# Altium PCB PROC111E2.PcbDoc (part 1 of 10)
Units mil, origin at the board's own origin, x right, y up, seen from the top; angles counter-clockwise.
Board outline 7700 x 2300 mil, 6 copper layers (Top Layer, GND 1, SIG 1, SIG 2, GND 2, Bottom Layer), stack 78.711 mil thick; 767 components, 596 nets, 2755 pads, 1578 vias.
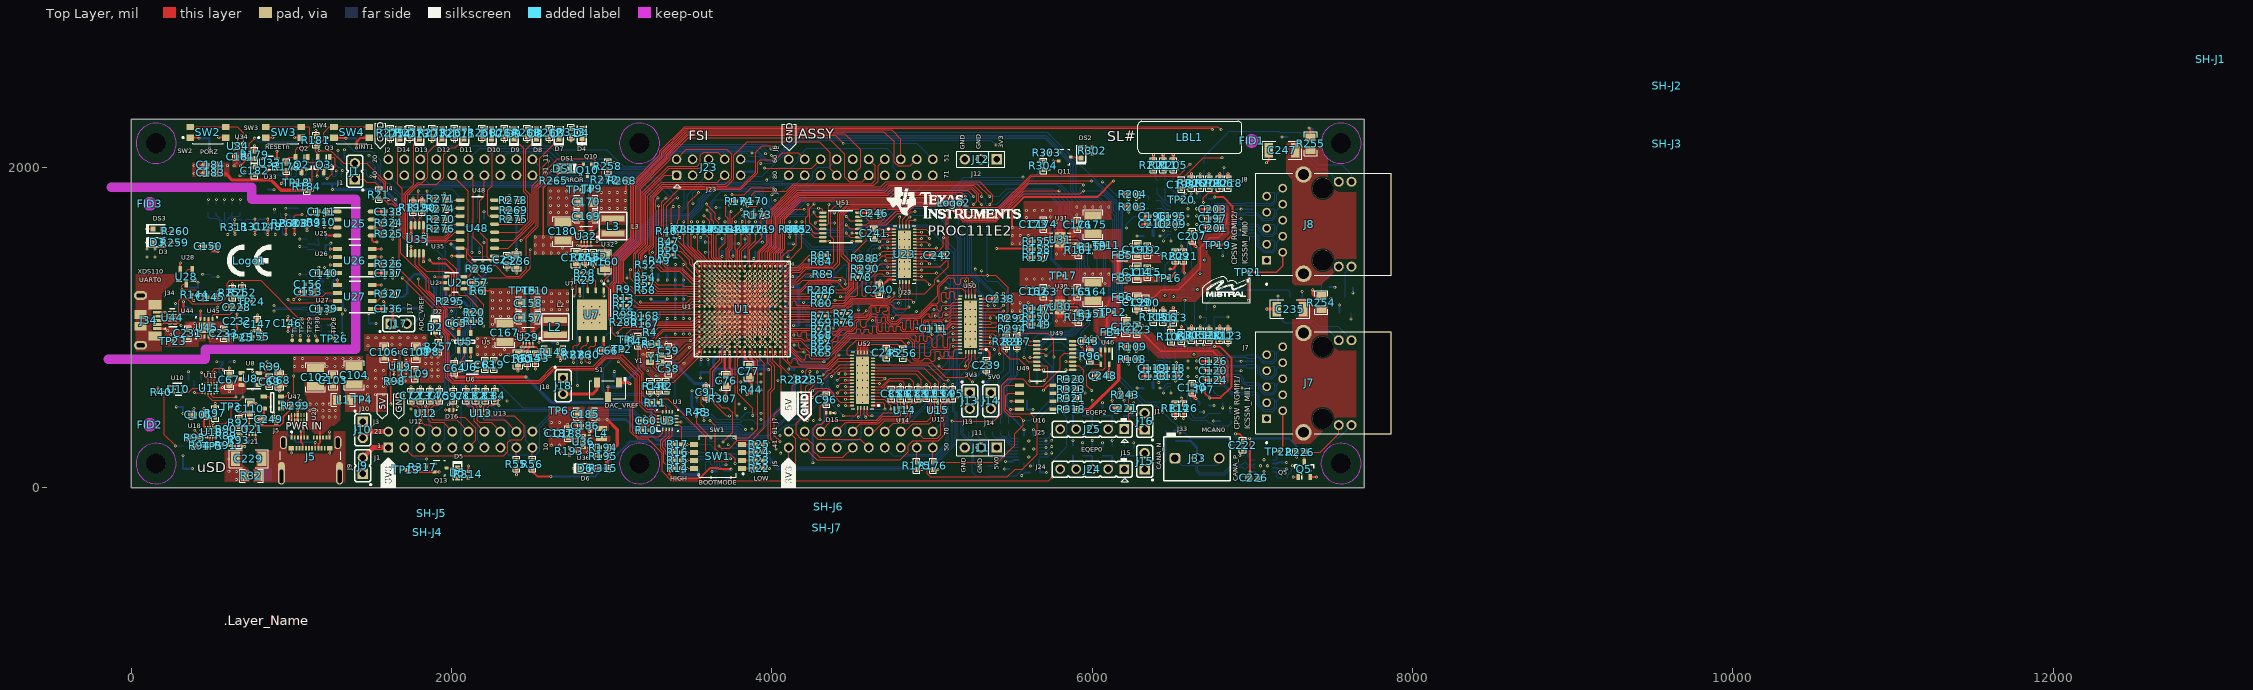
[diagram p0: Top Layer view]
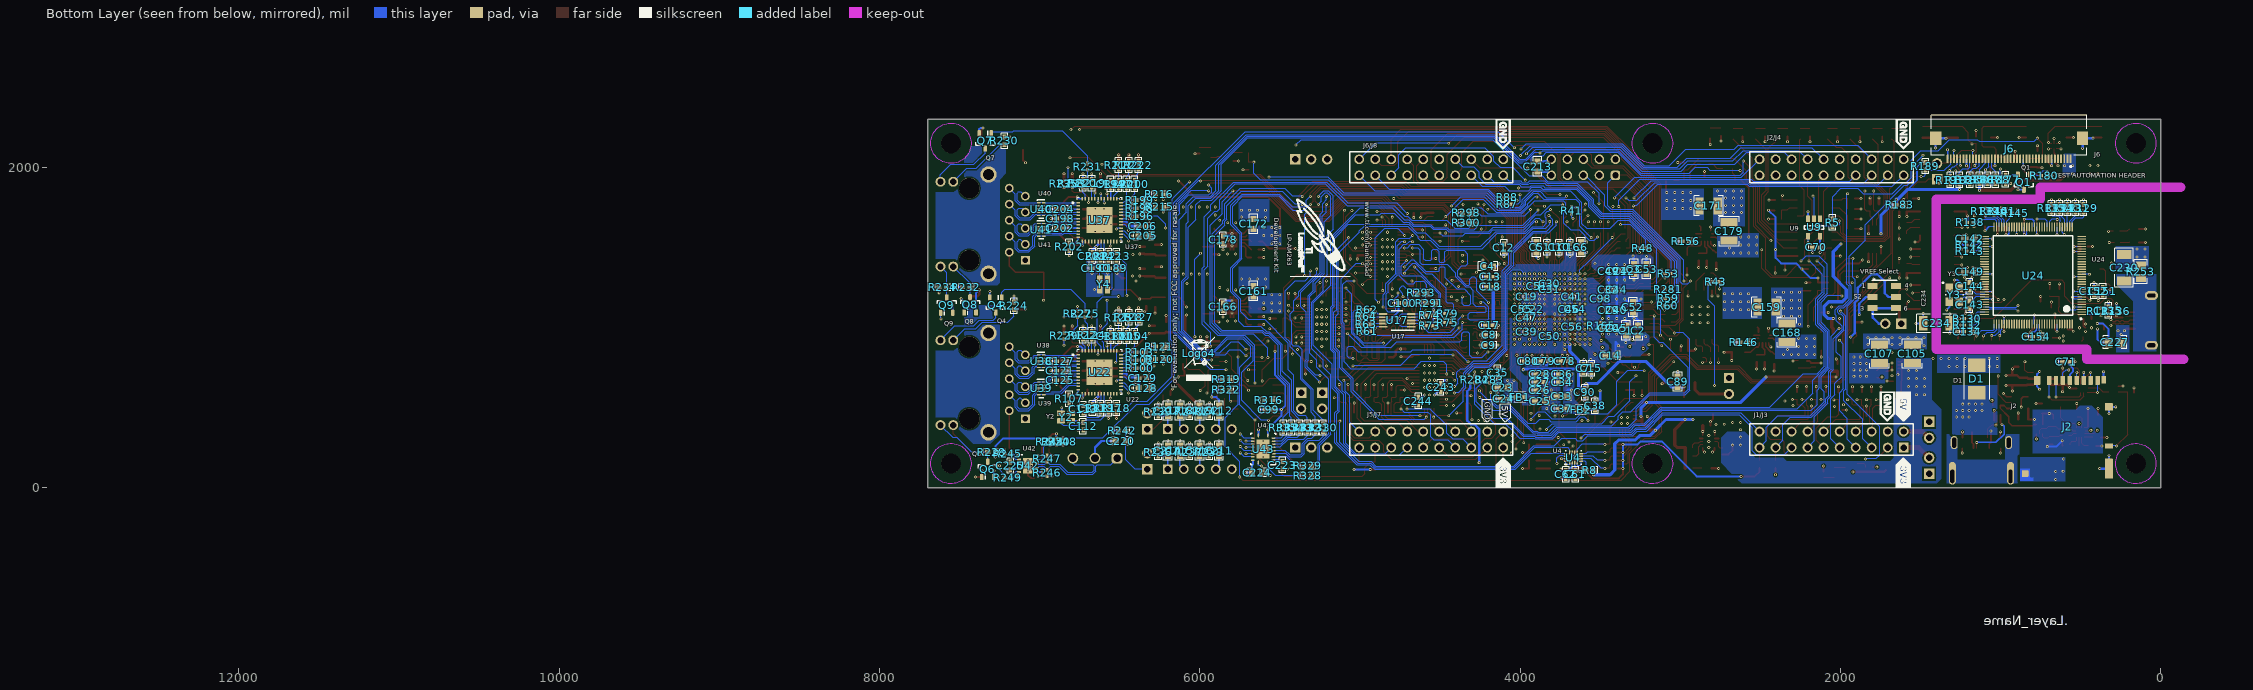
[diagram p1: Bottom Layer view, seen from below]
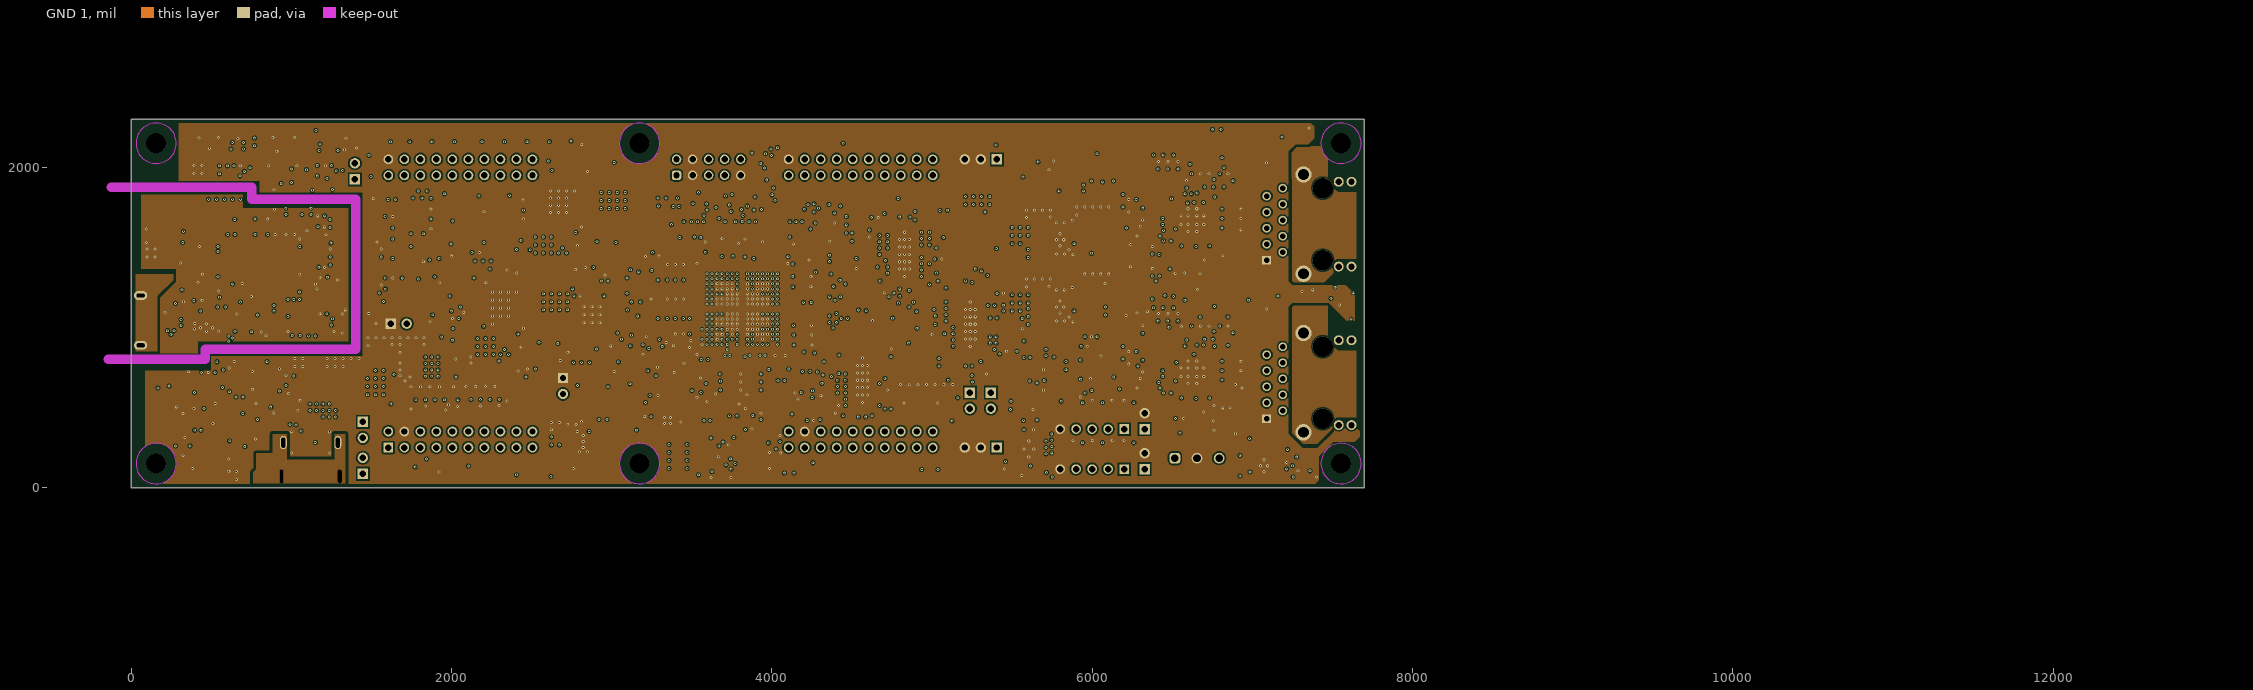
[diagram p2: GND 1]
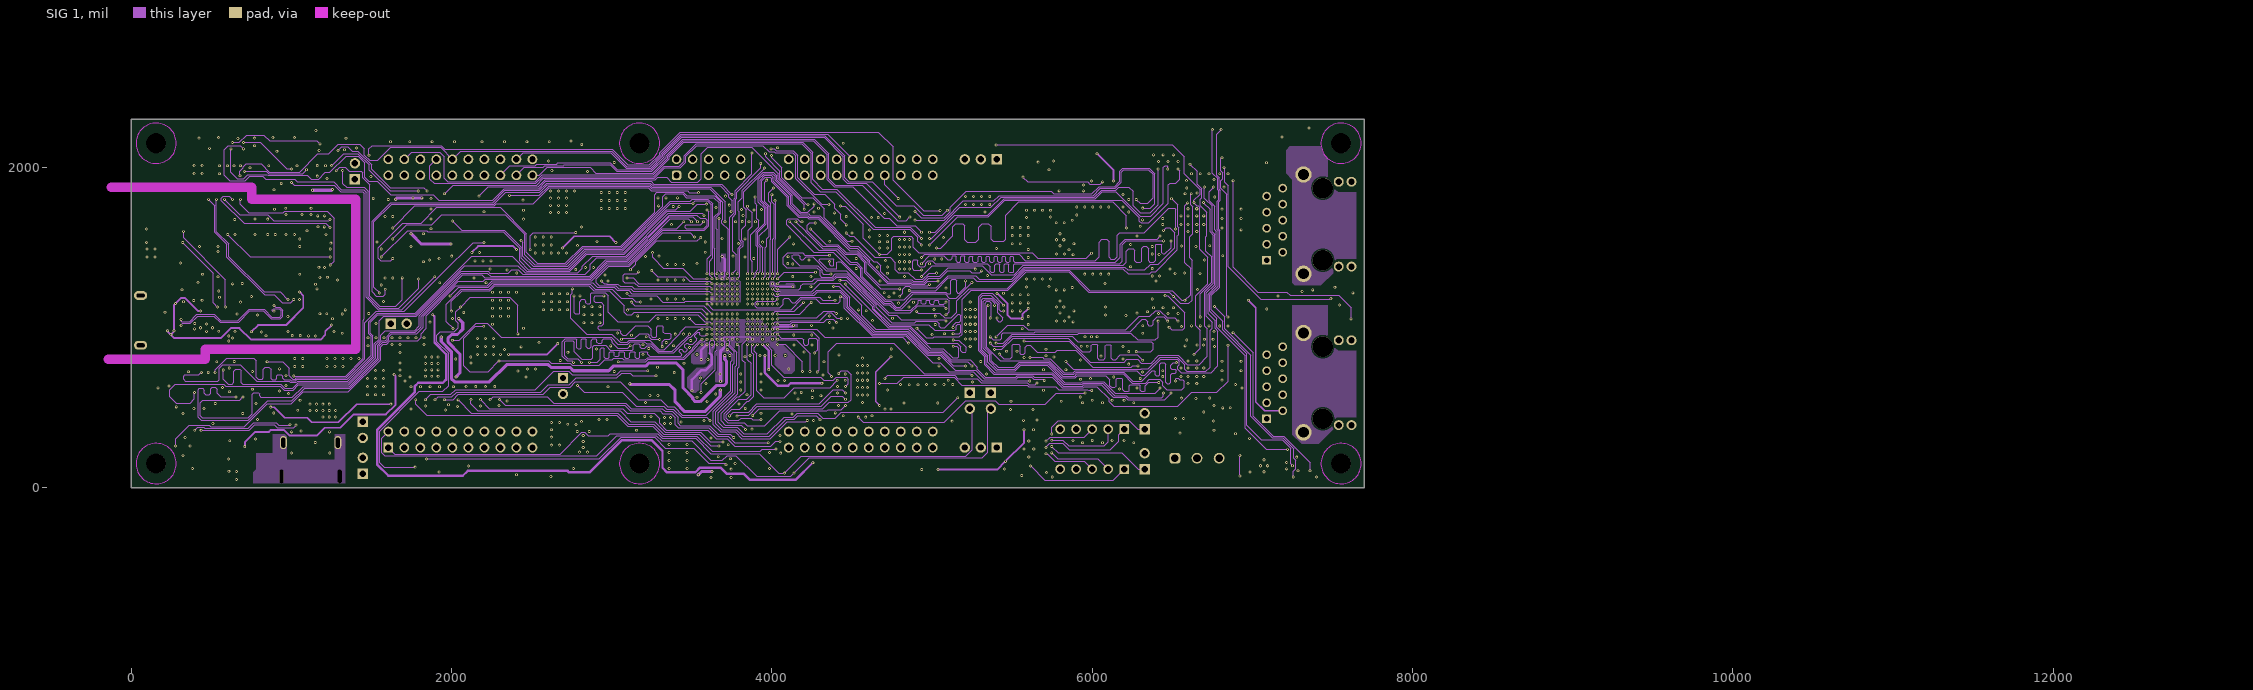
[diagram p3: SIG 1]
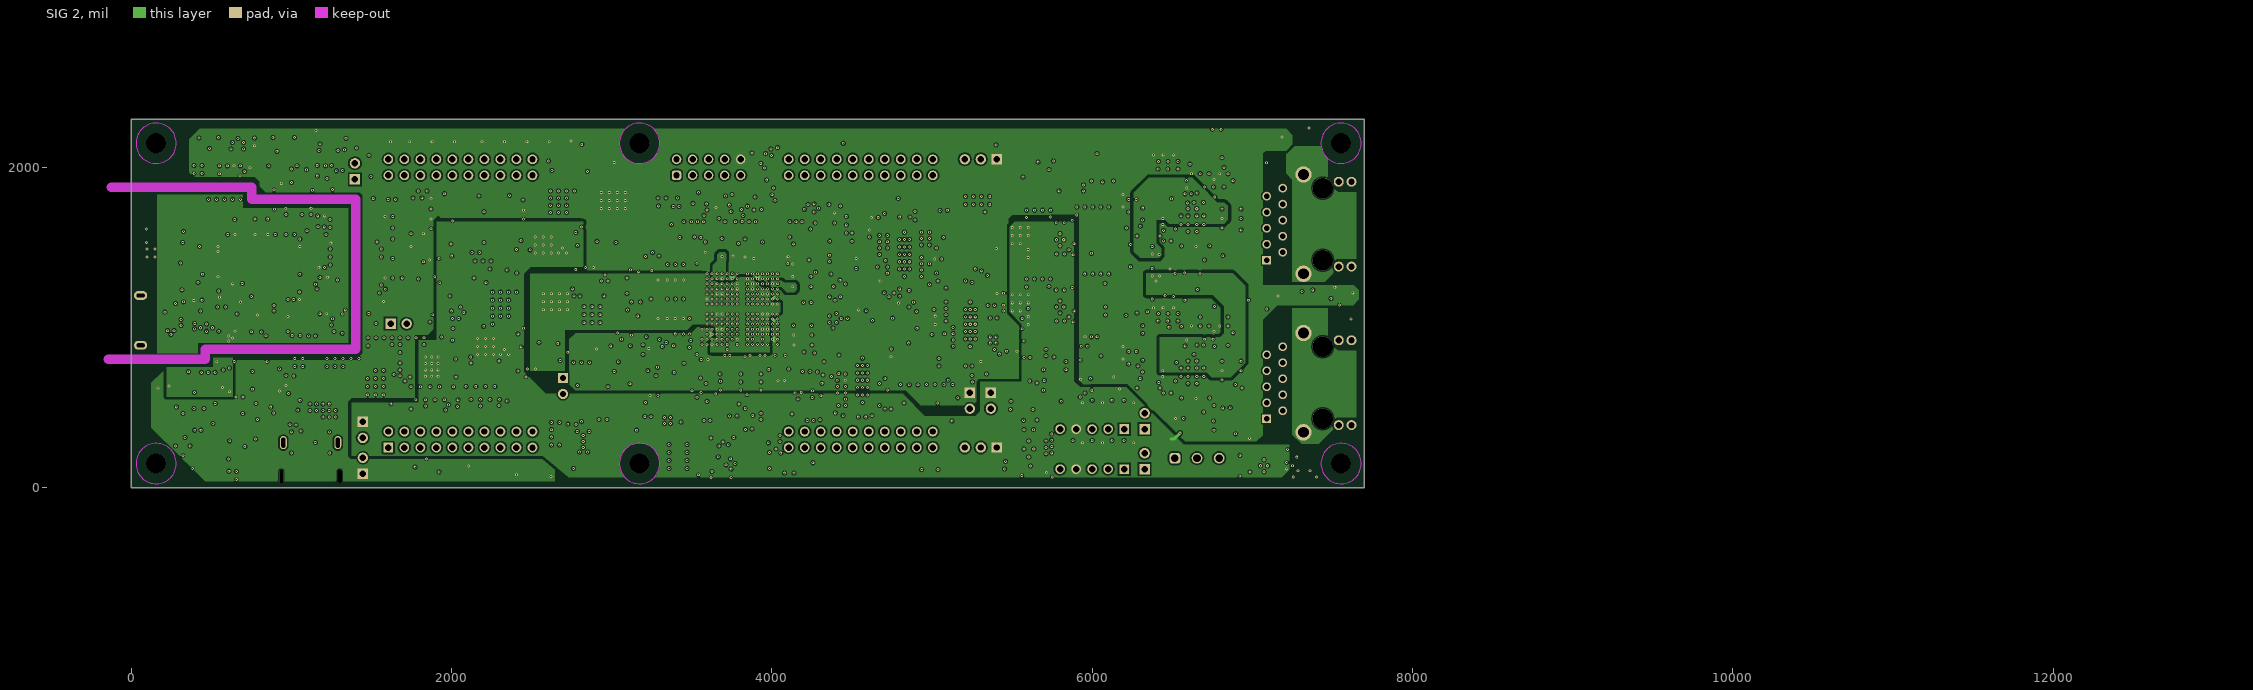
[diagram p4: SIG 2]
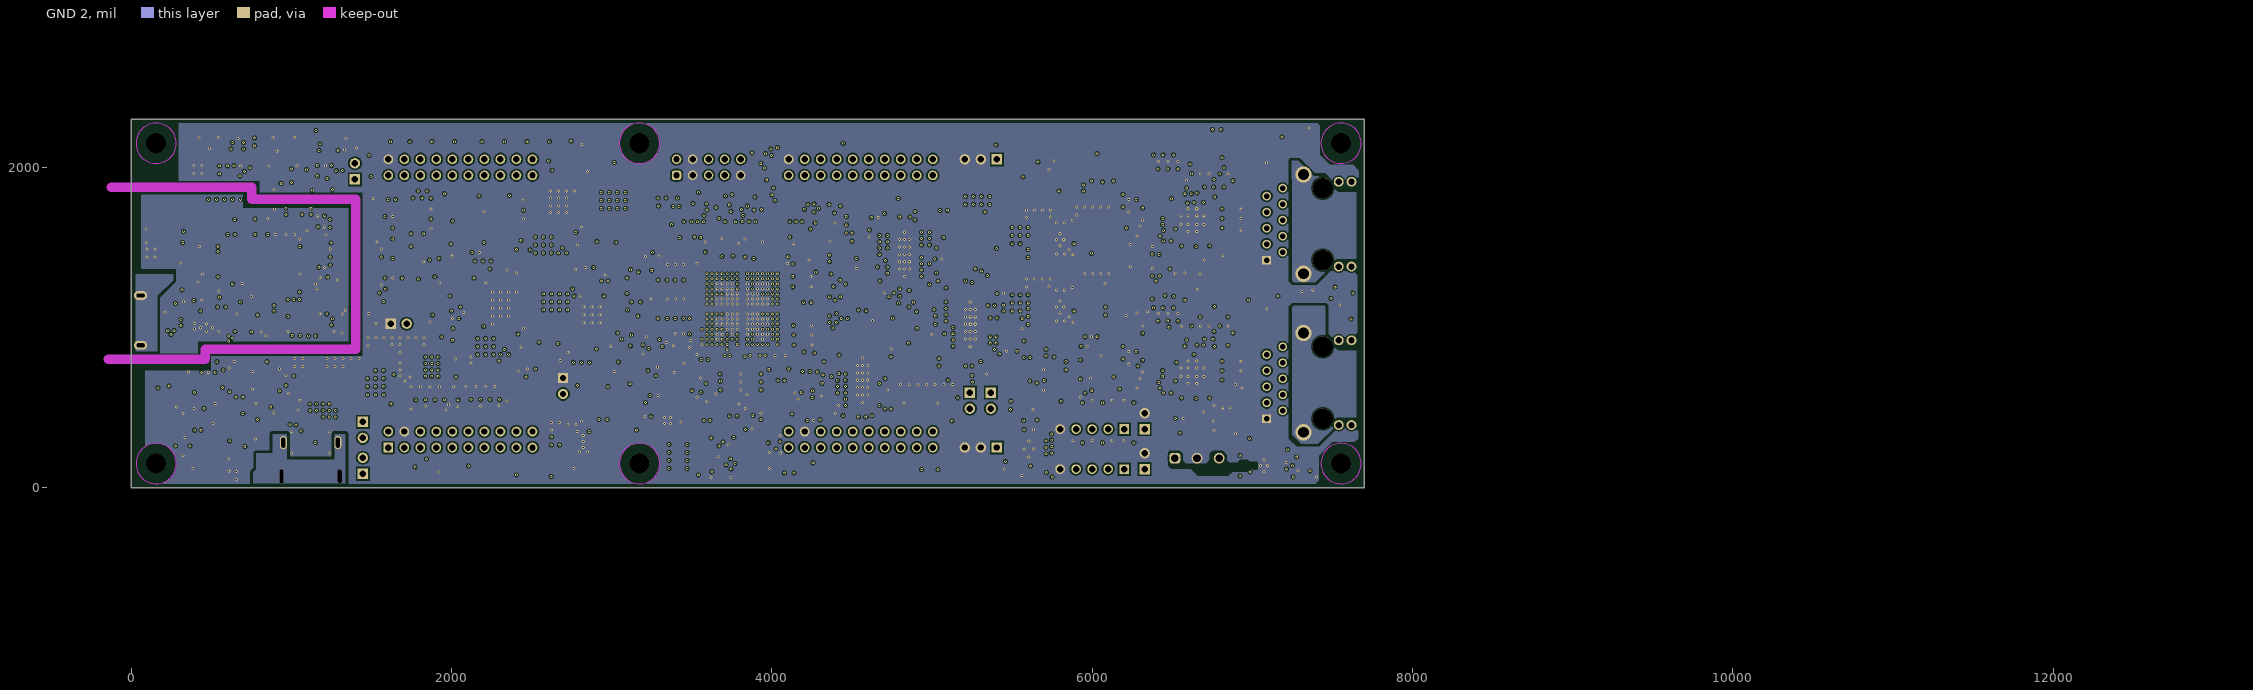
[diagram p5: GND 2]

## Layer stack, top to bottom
Top Solder: solder mask 0.4, Solder Resist, Dk 3.5
Top Layer: signal copper 1.4
Dielectric 1: prepreg 2.8, PP-006, Dk 4.1
GND 1: signal copper 1.3779
Dielectric 3: prepreg 2.8, PP-006, Dk 4.1
SIG 1: signal copper 1.3778
Dielectric1: core 59.2, FR-4 High Tg, Dk 4.8
SIG 2: signal copper 1.3778
Dielectric 4: prepreg 2.8, PP-006, Dk 4.1
GND 2: signal copper 1.3779
Dielectric 2: prepreg 2.8, PP-006, Dk 4.1
Bottom Layer: signal copper 1.4
Bottom Solder: solder mask 0.4, Solder Resist, Dk 3.5

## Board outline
0,0 0,2300 7700,2300 7700,0

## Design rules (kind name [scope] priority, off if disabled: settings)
AssemblyTestPointUsage [All] p1: valid=2
BoardOutlineClearance BoardOutlineClearance_MountingHoles [OnCopper and InComponentClass('Mounting Holes')] p1: gap=39.37 ignorepadtopadclearanceinfootprint=FALSE
BoardOutlineClearance BoardOutlineClearance_Poly [OnCopper and IsPoly] p2: gap=25 ignorepadtopadclearanceinfootprint=FALSE
BoardOutlineClearance [OnCopper and Not InComponentClass('Logo') and not InComponentClass('FiducialMark') and not InRegion(1000,500,4000,800) and not InPoly] p3: gap=40 ignorepadtopadclearanceinfootprint=FALSE
Clearance Clearance_Keepouts [IsKeepOut] p1: gap=1 ignorepadtopadclearanceinfootprint=FALSE
Clearance 4mil [WithinRoom('SOC_4mil')] p2: gap=4 ignorepadtopadclearanceinfootprint=TRUE except(15: Fill-Fill Fill-Poly Fill-Region Poly-Poly Poly-Region Region-Region)
Clearance ADC_EXT [(OnLayer('Top Layer') or OnLayer('Bottom Layer')) vs InNetClass('ADC0')] p3: gap=7.87 ignorepadtopadclearanceinfootprint=TRUE except(6: Via-Fill Via-Poly Via-Region; 10.6: Arc-Arc Arc-Track Track-Track; 18: Via-Via; 25: Fill-Fill Fill-Poly Fill-Region Poly-Poly Poly-Region Region-Region)
Clearance ADC_SIG1 [OnLayer('SIG 1') vs InNetClass('ADC0')] p4: gap=7.87 ignorepadtopadclearanceinfootprint=TRUE except(6: Via-Fill Via-Poly Via-Region; 9.5: Arc-Arc Arc-Track Track-Track; 18: Via-Via; 25: Fill-Fill Fill-Poly Fill-Region Poly-Poly Poly-Region Region-Region)
Clearance 100E_CLR_same [InDifferentialPairClass('100E')] p5: gap=7.87 ignorepadtopadclearanceinfootprint=TRUE except(7.7: Arc-Arc Arc-Track Track-Track; 10: Via-Fill Via-Poly Via-Region; 18: Via-Via; 25: Fill-Fill Fill-Poly Fill-Region Poly-Poly Poly-Region Region-Region)
Clearance 100E_CLR [InDifferentialPairClass('100E')] p6: gap=7.87 ignorepadtopadclearanceinfootprint=TRUE except(6: Via-Fill Via-Poly Via-Region; 16.2: Arc-Arc Arc-Track Track-Track; 18: Via-Via; 25: Fill-Fill Fill-Poly Fill-Region Poly-Poly Poly-Region Region-Region)
Clearance Clearance_Poly [InPolygon] p7: gap=10 ignorepadtopadclearanceinfootprint=TRUE except(6: Via-Fill Via-Poly Via-Region; 20: Fill-Fill Fill-Poly Fill-Region Poly-Poly Poly-Region Region-Region)
Clearance DIff_spacing [All vs InDifferentialPair('XDSET_1_D')] p8: gap=7.87 ignorepadtopadclearanceinfootprint=TRUE except(5: Arc-Arc Arc-Track Track-Track; 6: Via-Fill Via-Poly Via-Region; 18: Via-Via; 25: Fill-Fill Fill-Poly Fill-Region Poly-Poly Poly-Region Region-Region)
Clearance [All] p9: gap=7.87 ignorepadtopadclearanceinfootprint=TRUE except(5.3: Arc-Arc Arc-Track Track-Track; 6: SMDPad-SMDPad Via-Fill Via-Poly Via-Region; 7.4: Arc-SMDPad Track-SMDPad; 18: Via-Via; 25: Fill-Fill Fill-Poly Fill-Region Poly-Poly Poly-Region Region-Region)
ComponentClearance ComponentClearance_MountingHoles_FiducialMarks [InComponentClass('Mounting Holes') vs InComponentClass('FiducialMark')] p1: gap=50 collisioncheckmode=3 verticalgap=10 showdistances=FALSE
ComponentClearance ComponentClearance_Shunt [InComponentClass('Header') vs InComponentClass('Shunt')] p2: gap=0 collisioncheckmode=3 verticalgap=0 showdistances=FALSE
ComponentClearance ComponentClearance_Logo [InComponentClass('Logo')] p3: gap=30 collisioncheckmode=3 verticalgap=10 showdistances=FALSE
ComponentClearance ComponentClearance_ScrewToNut [(HasFootprint('NY PMS 440 0025 PH')) vs (HasFootprint('Keystone_1902C'))] p4: gap=5 collisioncheckmode=3 verticalgap=10 showdistances=FALSE
ComponentClearance ComponentClearance_MountingHoles [InComponentClass('Mounting Holes')] p5: gap=100 collisioncheckmode=3 verticalgap=100000 showdistances=FALSE
ComponentClearance ComponentClearance_SmallPassives [HasFootprint('0201*') or HasFootprint('0402*') or HasFootprint('0508') or HasFootprint('0603*') or HasFootprint('0612') or HasFootprint('0805*') or HasFootprint('0815*') or HasFootprint('0830*') or HasFootprint('1206*') or HasFootprint('1210*') or HasFootprint('1808*') or HasFootprint('1812*') or HasFootprint('1825*') or HasFootprint('2010*') or HasFootprint('2220*') or HasFootprint('2225*') or HasFootprint('2512*') or HasFootprint('2728*') or HasFootprint('3518*') vs HasFootprint('0201*') or HasFootprint('0402*') or HasFootprint('0508') or HasFootprint('0603*') or HasFootprint('0612') or HasFootprint('0805*') or HasFootprint('0815*') or HasFootprint('0830*') or HasFootprint('1206*') or HasFootprint('1210*') or HasFootprint('1808*') or HasFootprint('1812*') or HasFootprint('1825*') or HasFootprint('2010*') or HasFootprint('2220*') or HasFootprint('2225*') or HasFootprint('2512*') or HasFootprint('2728*') or HasFootprint('3518*')] p6: gap=10 collisioncheckmode=3 verticalgap=10 showdistances=FALSE
ComponentClearance ComponentClearance_THtoSMT [IsThruComponent vs IsSMTComponent] p7: gap=30 collisioncheckmode=3 verticalgap=30 showdistances=FALSE
ComponentClearance ComponentClearance_THtoTH [IsThruComponent vs IsThruComponent] p8: gap=20 collisioncheckmode=3 verticalgap=30 showdistances=FALSE
ComponentClearance [All] p9: gap=15 collisioncheckmode=3 verticalgap=15 showdistances=TRUE
DiffPairsRouting 90E [InDifferentialPair('XDSET_1_D')] p1: maxlimit=10 minlimit=5 mostfreqgap=10 toplayer_prefgap=5 toplayer_minwidth=4.2 toplayer_maxwidth=15 toplayer_prefwidth=4.2 midlayer1_mingap=6 midlayer1_maxgap=6 midlayer1_prefgap=6 midlayer1_minwidth=4 midlayer1_maxwidth=4 midlayer1_prefwidth=4 midlayer2_mingap=10 midlayer2_minwidth=15 midlayer2_maxwidth=15 midlayer2_prefwidth=15 midlayer3_mingap=10 midlayer3_minwidth=15 midlayer3_maxwidth=15 midlayer3_prefwidth=15 midlayer4_mingap=10 midlayer4_minwidth=15 midlayer4_maxwidth=15 midlayer4_prefwidth=15 bottomlayer_prefgap=5 bottomlayer_minwidth=4.2 bottomlayer_maxwidth=15 bottomlayer_prefwidth=4.2 maxuncoupledlength=500
DiffPairsRouting 120E [InDifferentialPair('CANA')] p2: maxlimit=10 minlimit=6.8 mostfreqgap=10 toplayer_prefgap=6.8 toplayer_minwidth=4.1 toplayer_maxwidth=15 toplayer_prefwidth=4.1 midlayer1_mingap=10 midlayer1_minwidth=15 midlayer1_maxwidth=15 midlayer1_prefwidth=15 midlayer2_mingap=10 midlayer2_minwidth=15 midlayer2_maxwidth=15 midlayer2_prefwidth=15 midlayer3_mingap=10 midlayer3_minwidth=15 midlayer3_maxwidth=15 midlayer3_prefwidth=15 midlayer4_mingap=10 midlayer4_minwidth=15 midlayer4_maxwidth=15 midlayer4_prefwidth=15 bottomlayer_prefgap=6.8 bottomlayer_minwidth=4.1 bottomlayer_maxwidth=15 bottomlayer_prefwidth=4.1 maxuncoupledlength=500
DiffPairsRouting 100E_DIFF [InDifferentialPairClass('100E')] p3: maxlimit=100 minlimit=7.7 mostfreqgap=10 toplayer_maxgap=7.7 toplayer_prefgap=7.7 toplayer_minwidth=4 toplayer_maxwidth=4 toplayer_prefwidth=4 midlayer1_mingap=8.1 midlayer1_maxgap=8.1 midlayer1_prefgap=8.1 midlayer1_minwidth=3.5 midlayer1_maxwidth=3.5 midlayer1_prefwidth=3.5 midlayer2_mingap=10 midlayer2_minwidth=15 midlayer2_maxwidth=15 midlayer2_prefwidth=15 midlayer3_mingap=10 midlayer3_minwidth=15 midlayer3_maxwidth=15 midlayer3_prefwidth=15 midlayer4_mingap=10 midlayer4_minwidth=15 midlayer4_maxwidth=15 midlayer4_prefwidth=15 bottomlayer_maxgap=7.7 bottomlayer_prefgap=7.7 bottomlayer_minwidth=4 bottomlayer_maxwidth=4 bottomlayer_prefwidth=4 maxuncoupledlength=1000
FabricationTestPointUsage TestPointUsage [All] p1: valid=2 allowmultiple=FALSE
FabricationTestpoint Testpoint [All] p1: side=3 testpointundercomponent=TRUE minsize=40 maxsize=100 preferedsize=60 minholesize=0 maxholesize=40 preferedholesize=32 testpointgrid=1 allowsidetop=TRUE allowsidebottom=TRUE usegrid=TRUE gridtolerance=0.01
FanoutControl Fanout_LCC [IsLCC] p1: bgadir=Out bgaviamode=Centered fanoutstyle=Auto fanoutdirection=Alternating viagrid=1 // Fanout_LCC (Default Rule)
FanoutControl Fanout_BGA [IsBGA] p2: bgadir=Out bgaviamode=Centered fanoutstyle=Auto fanoutdirection=Alternating viagrid=1 // Fanout_BGA (Default Rule)
FanoutControl Fanout_Default [All] p4: bgadir=Out bgaviamode=Centered fanoutstyle=Auto fanoutdirection=Alternating viagrid=1 // Fanout_Default (Default Rule)
FanoutControl Fanout_Small [(CompPinCount < 5)] p5: bgadir=Out bgaviamode=Centered fanoutstyle=Auto fanoutdirection=OutThenIn viagrid=1 // Fanout_Small (Default Rule)
HoleSize [All] p1: absolutevalues=TRUE maxlimit=251 minlimit=7.87 maxpercent=80.000 minpercent=20.000
MatchedLengths DIFF [All] p1: tolerance=2 checknetsindiffpair=TRUE checkdiffpairvsdiffpair=FALSE checkxsignals=FALSE checkothers=FALSE
MatchedLengths QSPI [InxSignalClass('QSPI_FLASH')] p2: tolerance=25 checknetsindiffpair=FALSE checkdiffpairvsdiffpair=TRUE checkxsignals=TRUE checkothers=TRUE
MatchedLengths ETH1_RX [InxSignalClass('ETH1_RX')] p3: tolerance=7.5 checknetsindiffpair=FALSE checkdiffpairvsdiffpair=TRUE checkxsignals=TRUE checkothers=TRUE
MatchedLengths ETH1_TX [InxSignalClass('ETH1_TX')] p4: tolerance=7.5 checknetsindiffpair=FALSE checkdiffpairvsdiffpair=TRUE checkxsignals=TRUE checkothers=TRUE
MatchedLengths ICSSM_MII0_RX [InxSignalClass('ICSSM_MII0_RX')] p5: tolerance=7.5 checknetsindiffpair=FALSE checkdiffpairvsdiffpair=TRUE checkxsignals=TRUE checkothers=TRUE
MatchedLengths AM263_RGMII1_TX [InxSignalClass('AM263_RGMII1_TX')] p6: tolerance=7.5 checknetsindiffpair=FALSE checkdiffpairvsdiffpair=TRUE checkxsignals=TRUE checkothers=TRUE
MatchedLengths PRO_PROU_GPIO(0-6) [InxSignalClass('PRO_PROU_GPIO(0-6)')] p7: tolerance=7.5 checknetsindiffpair=FALSE checkdiffpairvsdiffpair=TRUE checkxsignals=TRUE checkothers=TRUE
MatchedLengths PRO_PROU_GPIO(11-16) [InxSignalClass('PRO_PROU_GPIO(11-16)')] p8: tolerance=7.5 checknetsindiffpair=FALSE checkdiffpairvsdiffpair=TRUE checkxsignals=TRUE checkothers=TRUE
MatchedLengths AM263_RGMII1_RX [InxSignalClass('AM263_RGMII1_RX')] p9: tolerance=7.5 checknetsindiffpair=FALSE checkdiffpairvsdiffpair=TRUE checkxsignals=TRUE checkothers=TRUE
MatchedLengths ICSSM_MII0_TX [InxSignalClass('ICSSM_MII0_TX')] p10: tolerance=7.5 checknetsindiffpair=FALSE checkdiffpairvsdiffpair=TRUE checkxsignals=TRUE checkothers=TRUE
MatchedLengths ICSSM_MII1_TX [InxSignalClass('ICSSM_MII1_TX')] p11: tolerance=7.5 checknetsindiffpair=FALSE checkdiffpairvsdiffpair=TRUE checkxsignals=TRUE checkothers=TRUE
MatchedLengths ICSSM_MII1_RX [InxSignalClass('ICSSM_MII1_RX')] p12: tolerance=7.5 checknetsindiffpair=FALSE checkdiffpairvsdiffpair=TRUE checkxsignals=TRUE checkothers=TRUE
MatchedLengths "SD CARD" [InxSignalClass('MMC0')] p13: tolerance=25 checknetsindiffpair=FALSE checkdiffpairvsdiffpair=TRUE checkxsignals=TRUE checkothers=TRUE
MinimumAnnularRing MinimumAnnularRing_ThermalPadVias [IsVia and InAnyComponent] p1: minimumring=5.91
MinimumAnnularRing [All] p2: minimumring=5
MinimumSolderMaskSliver MinimumSolderMaskSliver_Logo [InComponentClass('Logo') vs InComponentClass('Logo')] p1: minsoldermaskwidth=0.7
PlaneConnect [All] p1: planeconnectstyle=Direct reliefexpansion=10 reliefentries=4 reliefconductorwidth=10 reliefairgap=10
PolygonConnect PolygonConnect_3 [All vs IsNamedPolygon('SIG 2-vusb_3v3')] p1: connectstyle=Direct reliefconductorwidth=10 reliefentries=4 polygonreliefangle="90 Angle" airgapwidth=10
PolygonConnect PolygonConnect_2 [All vs IsNamedPolygon('Top Layer-VBUS_TYPEC_5V0')] p2: connectstyle=Direct reliefconductorwidth=10 reliefentries=4 polygonreliefangle="90 Angle" airgapwidth=10
PolygonConnect PolygonConnect_1 [All vs IsNamedPolygon('Top Layer-VBUS_TYPEC_5V0')] p3: connectstyle=Direct reliefconductorwidth=10 reliefentries=4 polygonreliefangle="90 Angle" airgapwidth=10
PolygonConnect [All] p4: connectstyle=Direct reliefconductorwidth=10 reliefentries=4 polygonreliefangle="90 Angle" airgapwidth=10
RoomDefinition SOC_4mil [False] p1: confinementstyle=ConfineIn formatcopy=TRUE lockcomponents=FALSE outline 3515.64,815.87 4114.06,815.87 4114.06,1414.29 3515.64,1414.29
RoutingLayers [All] p1: top layer_v5=TRUE mid layer 1_v5=TRUE mid layer 2_v5=TRUE mid layer 3_v5=FALSE mid layer 4_v5=TRUE bottom layer_v5=TRUE
RoutingVias ThermalPadVias [IsVia and InAnyComponent] p1: holewidth=7.87 width=19.68 viastyle="Through Hole" minholewidth=7.87 minwidth=19.68 maxholewidth=12.99 maxwidth=23.62
RoutingVias [All] p2: holewidth=8 width=18 viastyle="Through Hole" minholewidth=8 minwidth=18 maxholewidth=8 maxwidth=18
SilkToBoardRegionClearance [Not ((IsComment or IsDesignator) And (Hide <> 'False')) and not InRegion(1000,500,4000,800)] p1:
SilkToSilkClearance SilkToSilkClearance_Pb-FreeLogo [(HasFootprint('Pb-Free_Overlay_Medium') OR HasFootprint('Pb-Free_Overlay_Small')) vs (HasFootprint('Pb-Free_Overlay_Medium') OR HasFootprint('Pb-Free_Overlay_Small'))] p1: silktosilkclearance=0
SilkToSilkClearance [All] p2: silktosilkclearance=3.94
SilkToSolderMaskClearance SilkToComponentPadClearance [(IsPad or IsFill or IsRegion) and Component] p1: minsilkscreentomaskgap=3.54 clearancetoexposedcopper=TRUE
SilkToSolderMaskClearance "Silk to Solder Mask Opening" [All] p2: minsilkscreentomaskgap=3 clearancetoexposedcopper=FALSE
SolderMaskExpansion [All] p1: expansion=1.97 istentingtop=FALSE
UnRoutedNet [All] p1: checkbadconnections=TRUE
Width 4mil_soc [WithinRoom('SOC_4mil')] p1: maxlimit=20 minlimit=4 preferedwidth=15 toplayer_prefwidth=4 midlayer1_prefwidth=4 midlayer3_minwidth=10 midlayer3_maxwidth=10 midlayer3_prefwidth=10 midlayer4_minwidth=10 midlayer4_maxwidth=10 midlayer4_prefwidth=10 bottomlayer_prefwidth=4 minimp=50.000000 maximp=50.000000 favimp=50.000000
Width "4 mil_mux" [WithinRoom('SOC_4mil_1') or  WithinRoom('SOC_4mil_2') or WithinRoom('SOC_4mil_3')] p2: maxlimit=15 minlimit=4.75 preferedwidth=10 toplayer_minwidth=5.3 toplayer_prefwidth=5.3 midlayer1_maxwidth=10 midlayer1_prefwidth=4.75 midlayer2_maxwidth=10 midlayer3_minwidth=5.3 midlayer3_maxwidth=10 midlayer4_minwidth=5.3 midlayer4_maxwidth=10 bottomlayer_minwidth=5.3 bottomlayer_prefwidth=5.3 minimp=50.000000 maximp=50.000000 favimp=50.000000
Width PWR [InNetClass('PWR')] p3: maxlimit=30 minlimit=6 preferedwidth=12 midlayer1_minwidth=8 midlayer2_minwidth=8 midlayer3_minwidth=8 midlayer4_minwidth=8 bottomlayer_minwidth=7 minimp=50.000000 maximp=50.000000 favimp=50.000000
Width [All] p4: maxlimit=100 minlimit=4.75 preferedwidth=5.3 toplayer_minwidth=5.3 midlayer1_prefwidth=4.75 midlayer2_minwidth=5.3 midlayer3_minwidth=5.3 midlayer4_minwidth=5.3 bottomlayer_minwidth=5.3 minimp=50.000000 maximp=50.000000 favimp=50.000000 checkconnectedcopper=TRUE
13 further rules are at their usual default settings.

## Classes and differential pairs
net class POWER: VBUS_XDS_5V0
component class PROC111_XDS110_2: C134 C135 C136 C137 C138 C139 C140 C141 C142 C143 C144 C145 C146 C147 C148 C149 C150 C151 C152 C153 C154 C155 C156 C234 D3 DS3 R129 R130 R131 R132 R133 R134 R135 R136 R137 R138 R139 R140 R141 R142 R143 R144 R145 R259 R260 R261 R308 R309 R310 R311 R312 R324 R325 R326 R327 TP27 TP28 TP29 TP30 U24 U25 U26 U27 U28 Y3
component class PROC111_XDS110_1: C227 C228 C230 C231 C232 C233 J34 R251 R252 R253 TP23 TP24 TP25 TP26 U44 U45
component class PROC111_Test_Automation: C183 C184 C185 C186 C187 C188 J1 J6 L4 R21 R182 R183 R184 R185 R186 R187 R188 R189 R190 R191 R192 R193 R194 R195 TP18 U35 U36
component class PROC111_System_Power_2: C157 C158 C159 C160 C161 C162 C163 C164 C165 C166 C167 C168 C169 C170 C171 C172 C173 C174 C175 C176 C177 C178 C179 C180 L2 L3 R146 R147 R148 R149 R150 R151 R152 R153 R154 R155 R156 R157 R158 R159 R160 R161 R162 R163 R295 R296 TP8 TP9 TP10 TP11 TP12 TP13 TP14 TP15 TP16 TP17 U29 U30 U31 U32
component class PROC111_System_Power_1: C101 C102 C103 C104 C105 C106 C107 C108 C109 C110 C229 C249 D1 J5 J11 J12 L1 R32 R89 R90 R91 R92 R93 R94 R95 R97 R98 R299 TP3 TP4 TP5 TP6 U18 U19 U20 U21 U47
component class PROC111_Push_Buttons: C181 C182 Q1 Q2 Q3 R177 R178 R179 R180 R181 SW2 SW3 SW4 U33 U34
component class PROC111_LED: C236 C237 D2 D4 D5 D6 D7 D8 D9 D10 D11 D12 D13 D14 DS1 DS2 Q10 Q11 Q13 R257 R262 R263 R264 R265 R266 R267 R268 R269 R270 R271 R272 R273 R274 R275 R276 R277 R278 R279 R302 R303 R304 R313 R314 R315 R317 U48
component class PROC111_Ehernet_RJ45_2: C247 J8 Q7 Q8 Q9 R230 R231 R232 R233 R234 R235 R255 TP22 U40 U41
component class PROC111_Ehernet_RJ45_1: C235 J7 Q4 Q5 Q6 R224 R225 R226 R227 R228 R229 R254 TP21 U38 U39
component class PROC111_Ehernet_PHY_2: C189 C190 C191 C192 C193 C194 C195 C196 C197 C198 C199 C200 C201 C202 C203 C204 C205 C206 C207 C208 C209 C210 FB5 FB6 R196 R197 R198 R199 R200 R201 R202 R203 R204 R205 R206 R207 R208 R209 R210 R211 R212 R213 R214 R215 R216 R217 R218 R219 R220 R221 R222 R223 R306 TP19 TP20 U37 Y4
component class PROC111_Ehernet_PHY_1: C112 C113 C114 C115 C116 C117 C118 C119 C120 C121 C122 C123 C124 C125 C126 C127 C128 C129 C130 C131 C132 C133 C240 C241 C242 FB3 FB4 R100 R101 R102 R103 R104 R105 R106 R107 R108 R109 R110 R111 R112 R113 R114 R115 R116 R117 R118 R119 R120 R121 R122 R123 R124 R125 R126 R127 R128 R291 R292 R293 R294 R305 TP7 U22 U50 Y2
component class PROC111_Breakout_Headers: C211 C212 C213 C214 C215 C216 C217 C218 C219 C220 C221 C222 C223 C224 C225 C226 J15 J16 J17 J18 J23 J24 J25 J33 R236 R237 R238 R239 R240 R241 R242 R243 R244 R245 R246 R247 R248 R249 R250 R328 R329 R330 R331 R332 R333 R334 R335 U42 U43
component class PROC111_Boosterpack_Headers: C243 C244 C245 C246 J1/J3 J2/J4 J5/J7 J6/J8 J9 J10 J13 J14 R256 R298 R300 U51 U52
component class PROC111_AM263x_Serial_Connectivity: R164 R165 R166 R167 R168 R169 R170 R171 R172 R173 R174 R175 R176 R297
component class PROC111_AM263x_7_PRU: C43 C111 C238 C239 C248 R71 R72 R73 R74 R75 R76 R77 R78 R79 R80 R81 R82 R83 R84 R85 R86 R87 R88 R96 R286 R287 R288 R289 R290 U23 U46 U49
component class PROC111_AM263x_6_RGMII_MII: C100 R61 R62 R63 R64 R65 R66 R67 R68 R69 R70 U17
component class PROC111_AM263x_5_ePWM_eQEP_FSI: R9 R12 R13 R46 R47 R48 R49 R50 R51 R52 R53 R54 R55 R56 R57 R58 R59 R60 R99 R280 R281 R282 R283 R284 R285
component class PROC111_AM263x_3_QSPI_MMC: C66 C67 C68 C69 C70 C71 J2 R26 R27 R28 R29 R30 R31 R33 R34 R35 R36 R37 R38 R39 R40 R41 R42 R43 U7 U8 U9 U10 U11
component class PROC111_AM263x_2_Clock_Reset_Boot_JTAG: C57 C58 C59 C60 C61 C62 C63 C64 C65 C99 R4 R5 R6 R7 R8 R10 R11 R14 R15 R16 R17 R18 R19 R20 R22 R23 R24 R25 R258 R316 R318 R319 R320 R321 R322 R323 SW1 TP1 TP2 U2 U3 U4 U5 U6 U16 Y1
component class PROC111_AM263x_1_Power: C1 C2 C3 C4 C5 C6 C7 C8 C9 C10 C11 C12 C13 C14 C15 C16 C17 C18 C19 C20 C21 C22 C23 C24 C25 C26 C27 C28 C29 C30 C31 C32 C33 C34 C35 C36 C37 C38 C39 C40 C41 C42 C44 C45 C46 C47 C48 C49 C50 C51 C52 C53 C54 C55 C56 C98 FB1 FB2 R1 R2
component class PROC111_AM263x_4_ADC_DAC: C72 C73 C74 C75 C76 C77 C78 C79 C80 C81 C82 C83 C84 C85 C86 C87 C88 C89 C90 C91 C92 C93 C94 C95 C96 C97 D15 D16 R3 R44 R45 R307 S1 S2 U1 U12 U13 U14 U15
component class PROC111_Hardware: FID1 FID2 FID3 LBL1 Logo1 Logo2 Logo3 Logo4 SH-J1 SH-J2 SH-J3 SH-J4 SH-J5 SH-J6 SH-J7 ZZ1 ZZ2 ZZ3 ZZ4
differential pair XDSET_1_D: +XDSET_1_D_P -XDSET_1_D_N
differential pair ETH2_TD_D: +ETH2_TD_D_P -ETH2_TD_D_N
differential pair ETH2_TD_C: +ETH2_TD_C_P -ETH2_TD_C_N
differential pair ETH2_TD_B: +ETH2_TD_B_P -ETH2_TD_B_N
differential pair ETH2_TD_A: +ETH2_TD_A_P -ETH2_TD_A_N
differential pair ETH1_TD_D: +ETH1_TD_D_P -ETH1_TD_D_N
differential pair ETH1_TD_C: +ETH1_TD_C_P -ETH1_TD_C_N
differential pair ETH1_TD_B: +ETH1_TD_B_P -ETH1_TD_B_N
differential pair ETH1_TD_A: +ETH1_TD_A_P -ETH1_TD_A_N
differential pair CANA: +CANA_P -CANA_N

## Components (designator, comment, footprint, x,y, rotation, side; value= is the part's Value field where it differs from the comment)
C1 "C1608X7S1A335K080AC" 0603 3338.57,980.78 r270 bottom value=3.3uF
C2 "C1608X7S1A335K080AC" 0603 3262.14,980.78 r270 bottom value=3.3uF
C3 "C1608X7S1A335K080AC" 0603 3288.51,1364.76 r90 bottom value=3.3uF
C4 "C1608X7S1A335K080AC" 0603 4200,1381.81 r0 bottom value=3.3uF
C5 "C1608X7S1A335K080AC" 0603 3896.57,1501.5 r90 bottom value=3.3uF
C6 "C1608X7S1A335K080AC" 0603 3619.13,1501.5 r90 bottom value=3.3uF
C7 "GRM155R70J104KA01D" 0402 3603.63,743.75 r270 bottom value=0.1uF
C8 "GRM155R70J104KA01D" 0402 4192.18,952.97 r0 bottom value=0.1uF
C9 "GRM155R70J104KA01D" 0402 4193.67,890 r0 bottom value=0.1uF
C10 "GRM155R70J104KA01D" 0402 3756.08,1499.91 r90 bottom value=0.1uF
C11 "GRM155R70J104KA01D" 0402 3831.66,1499.91 r90 bottom value=0.1uF
C12 "GRM155R70J104KA01D" 0402 4100.67,1498.22 r90 bottom value=0.1uF
C13 "GRM155R70J104KA01D" 0402 4186.18,1317.07 r0 bottom value=0.1uF
C14 "C1608X7S1A335K080AC" 0603 3435,824.72 r180 bottom value=3.3uF
C15 "GRM155R70J104KA01D" 0402 3553.63,743.75 r270 bottom value=0.1uF
C16 "GRM155R70J104KA01D" 0402 3688.87,1499.91 r90 bottom value=0.1uF
C17 "GRM155R70J104KA01D" 0402 4190.85,1013.32 r0 bottom value=0.1uF
C18 "GRM155R70J104KA01D" 0402 4186.18,1254.06 r0 bottom value=0.1uF
C19 "GRM033C80J105ME05D" FP-GRM033C80J105ME05D_0201-MFG 3956.58,1193.07 r90 bottom value=1µF
C20 "GRM033C80J105ME05D" FP-GRM033C80J105ME05D_0201-MFG 3445.84,994.56 r90 bottom value=1µF
C21 "GRM033C80J105ME05D" FP-GRM033C80J105ME05D_0201-MFG 3395.84,1352.29 r270 bottom value=1µF
C22 "GRM033C80J105ME05D" FP-GRM033C80J105ME05D_0201-MFG 3916.09,1115.08 r0 bottom value=1µF
C23 "C1608X7S1A335K080AC" 0603 4107.94,624.92 r0 bottom value=3.3uF
C24 "GRM155R70J104KA01D" 0402 4100.96,554.26 r0 bottom value=0.1uF
C25 "C1608X7S1A335K080AC" 0603 3875,540.45 r180 bottom value=3.3uF
C26 "GRM155R70J104KA01D" 0402 3875.31,608.97 r180 bottom value=0.1uF
C27 "GRM155R70J104KA01D" 0402 3875.31,658.97 r180 bottom value=0.1uF
C28 "GRM155R70J104KA01D" 0402 3875.31,708.97 r180 bottom value=0.1uF
C29 "GRM033C80J105ME05D" FP-GRM033C80J105ME05D_0201-MFG 3445.84,1108.91 r270 bottom value=1µF
C30 "GRM033C80J105ME05D" FP-GRM033C80J105ME05D_0201-MFG 3815,1273.75 r180 bottom value=1µF
C31 "GRM033C80J105ME05D" FP-GRM033C80J105ME05D_0201-MFG 3814.85,1239.57 r180 bottom value=1µF
C32 "GRM033C80J105ME05D" FP-GRM033C80J105ME05D_0201-MFG 3445.84,1234.32 r90 bottom value=1µF
C33 "GRM188Z71A475ME15D" 0603 3738.88,569.08 r0 bottom value=4.7uF
C34 "GRM155R70J104KA01D" 0402 3736.38,658.97 r0 bottom value=0.1uF
C35 "GRM155R70J104KA01D" 0402 4139.44,717.13 r270 bottom value=0.1uF
C36 "GRM155R70J104KA01D" 0402 3736.38,708.97 r0 bottom value=0.1uF
C37 "GRM155R70J104KA01D" 0402 3739.61,493 r0 bottom value=0.1uF
C38 "GRM155R70J104KA01D" 0402 3531.39,509.65 r90 bottom value=0.1uF
C39 "GRM033C80J105ME05D" FP-GRM033C80J105ME05D_0201-MFG 3956.58,973 r90 bottom value=1µF
C40 "GRM033C80J105ME05D" FP-GRM033C80J105ME05D_0201-MFG 3395.84,1108.91 r270 bottom value=1µF
C41 "GRM033C80J105ME05D" FP-GRM033C80J105ME05D_0201-MFG 3673,1193.07 r90 bottom value=1µF
C42 "GRM033C80J105ME05D" FP-GRM033C80J105ME05D_0201-MFG 3348.24,1352.29 r270 bottom value=1µF
C43 "GRM155R71E104KE14D" 0402 5975,914.8 r180 top value=0.1uF
C44 "GRM033C80J105ME05D" FP-GRM033C80J105ME05D_0201-MFG 3395.84,1234.06 r90 bottom value=1µF
C45 "GRM033C80J105ME05D" FP-GRM033C80J105ME05D_0201-MFG 3395.84,994.56 r90 bottom value=1µF
C46 "GRM033C80J105ME05D" FP-GRM033C80J105ME05D_0201-MFG 3693.17,1115.1 r270 bottom value=1µF
C47 "GRM033C80J105ME05D" FP-GRM033C80J105ME05D_0201-MFG 3956.58,1060.9 r90 bottom value=1µF
C48 "GRM155R70J104KA01D" 0402 3287.47,633.24 r270 top value=0.1uF
C49 "GRM033Z71C104KE14D" 0201 3445.84,1352.29 r90 bottom value=0.1uF
C50 "GRM033Z71C104KE14D" 0201 3814.85,946.1 r90 bottom value=0.1uF
C51 "GRM033Z71C104KE14D" 0201 3892.96,1257.37 r0 bottom value=0.1uF
C52 "C1608X7S1A335K080AC" 0603 3295,1126.61 r90 bottom value=3.3uF
C53 "C1608X7S1A335K080AC" 0603 3210,1364.76 r90 bottom value=3.3uF
C54 "GRM033Z71C104KE14D" 0201 3654.78,1115.1 r90 bottom value=0.1uF
C55 "GRM033Z71C104KE14D" 0201 3990,1115.08 r180 bottom value=0.1uF
C56 "GRM033Z71C104KE14D" 0201 3673,1004.38 r90 bottom value=0.1uF
C57 "GRM155R71E104KE14D" 0402 2162.4,1279.45 r180 top value=0.1uF
C58 "GRM1555C1E120JA01D" 0402 3355,741.21 r270 top value=12pF
C59 "GRM1555C1E120JA01D" 0402 3355,854.33 r90 top value=12pF
C60 "GRM155R71E104KE14D" 0402 3215,418.33 r0 top value=0.1uF
C61 "GRM155R71E104KE14D" 0402 3653.69,81.97 r90 bottom value=0.1uF
C62 "GRM155R71E104KE14D" 0402 3713.69,81.97 r90 bottom value=0.1uF
C63 "GRM155R71E103KA01D" 0402 2207.84,767.39 r90 top value=0.01uF
C64 "GRM155R71E104KE14D" 0402 2017.57,746.48 r270 top value=0.1uF
C65 "GRM155R71E104KE14D" 0402 2029.22,1024.86 r0 top value=0.1uF
C66 "GRM155R71E104KE14D" 0402 2973.62,854.15 r180 top value=0.1uF
C67 "GRM188Z71C475KE21D" 0603 611.03,672.69 r90 top value=4.7uF
C68 "C1608X7S1A335K080AC" 0603 924.76,669.66 r90 top value=3.3uF
C69 "GRM155R70J104KA01D" 0402 862.1,661.79 r90 top value=0.1uF
C70 "GRM155R71E104KE14D" 0402 2149.39,1500 r180 bottom value=0.1uF
C71 "GRM155R71E104KE14D" 0402 587.8,785.43 r180 bottom value=0.1uF
C72 "GRM155R70J104KA01D" 0402 1745,571.95 r90 top value=0.1uF
C73 "GRM155R70J104KA01D" 0402 1805,571.95 r90 top value=0.1uF
C74 "GRM155R70J104KA01D" 0402 1865,571.95 r90 top value=0.1uF
C75 "GRM155R70J104KA01D" 0402 1924,571.95 r90 top value=0.1uF
C76 "GRM188Z71A475ME15D" 0603 3713.17,666.5 r270 top value=4.7uF
C77 "GRM188Z71A475ME15D" 0603 3855,727.37 r270 top value=4.7uF
C78 "GRM155R70J104KA01D" 0402 3720.36,789.94 r0 bottom value=0.1uF
C79 "GRM155R70J104KA01D" 0402 3844.81,789.94 r0 bottom value=0.1uF
C80 "GRM155R70J104KA01D" 0402 3948.62,789.94 r180 bottom value=0.1uF
C81 "GRM155R70J104KA01D" 0402 2090,572.47 r90 top value=0.1uF
C82 "GRM155R70J104KA01D" 0402 2150,572.47 r90 top value=0.1uF
C83 "GRM155R70J104KA01D" 0402 2210,572.47 r90 top value=0.1uF
C84 "GRM155R70J104KA01D" 0402 2269,572.47 r90 top value=0.1uF
C85 "GRM155R70J104KA01D" 0402 4747.11,585.15 r90 top value=0.1uF
C86 "GRM155R70J104KA01D" 0402 4802.11,585.15 r90 top value=0.1uF
C87 "GRM155R70J104KA01D" 0402 4856.7,585.15 r90 top value=0.1uF
C88 "GRM155R70J104KA01D" 0402 4911.11,585.15 r90 top value=0.1uF
C89 "GRM188Z71A475ME15D" 0603 3015,660 r90 bottom value=4.7uF
C90 "GRM155R70J104KA01D" 0402 3595,594.91 r270 bottom value=0.1uF
C91 "GRM155R70J104KA01D" 0402 3590,595 r270 top value=0.1uF
C92 "GRM155R70J104KA01D" 0402 4965,586 r90 top value=0.1uF
C93 "GRM155R70J104KA01D" 0402 5017.97,585.3 r90 top value=0.1uF
C94 "GRM155R70J104KA01D" 0402 5073,585.3 r90 top value=0.1uF
C95 "GRM155R70J104KA01D" 0402 5128.54,585.3 r90 top value=0.1uF
C96 "GRM155R70J104KA01D" 0402 4339.72,549.93 r90 top value=0.1uF
C97 "GRM155R70J104KA01D" 0402 2010,571.38 r90 top value=0.1uF
C98 "GRM155R70J104KA01D" 0402S 3494.98,1177.95 r180 bottom value=0.1uF
C99 "GRM155R71E104KE14D" 0402 5570,487.03 r180 bottom value=0.1uF
C100 "GRM155R71E104KE14D" 0402 4735,1152.06 r0 bottom value=0.1uF
C101 "GCM188R71C104KA37J" 0603 420.79,454.11 r180 top value=0.1uF
C102 "GRM32ER7YA106KA12K" 1210_270 1149.04,689.61 r90 top value=10uF
C103 "GRM188R72A104KA35J" 0603 1260,669.61 r90 top value=0.1uF
C104 "GRM32ER7YA106KA12K" 1210_270 1390.89,700.82 r90 top value=10uF
C105 "GRM32ER7YA106KA12K" 1210_270 1550,835 r90 bottom value=10uF
C106 "GCM188R71C104KA37J" 0603 1579.67,844.07 r90 top value=0.1uF
C107 "GRM32ER7YA106KA12K" 1210_270 1755.65,835 r90 bottom value=10uF
C108 "GCM188R71C104KA37J" 0603 1776.91,844.07 r90 top value=0.1uF
C109 "GRM155R71C102KA01D" 0402 1771.58,710 r270 top value=1000pF
C110 "GCM188R71C104KA37J" 0603 740,493.54 r90 top value=0.1uF
C111 "GRM155R71E104KE14D" 0402 5009,992.82 r0 top value=0.1uF
C112 "GRM1555C1E120JA01D" 0402 6728.01,381.88 r270 bottom value=12pF
C113 "GRM1555C1E120JA01D" 0402 6728.01,489.12 r90 bottom value=12pF
C114 "GRM188Z71A106MA73D" 0603 6279,1343.28 r90 top value=10uF
C115 "GRM155R70J103KA01D" 0402 6344,1343.28 r90 top value=0.01uF
C116 "GRM155R70J105MA12D" 0402 6556.28,941.71 r90 top value=1uF
C117 "GRM155R70J104KA01D" 0402 6556.28,945.08 r90 bottom value=0.1uF
C118 "GRM155R70J105MA12D" 0402 6493.94,745.04 r0 top value=1uF
C119 "GRM155R70J104KA01D" 0402 6374.14,745.04 r180 top value=0.1uF
C120 "GRM155R70J105MA12D" 0402 6755.41,729.88 r180 top value=1uF
C121 "GRM155R70J104KA01D" 0402 6870.21,729.88 r0 bottom value=0.1uF
C122 "GRM188Z71A106MA73D" 0603 6210,1003.65 r90 top value=10uF
C123 "GRM155R70J103KA01D" 0402 6280.09,987.15 r90 top value=0.01uF
C124 "GRM155R70J105MA12D" 0402 6755.41,670.83 r180 top value=1uF
C125 "GRM155R70J104KA01D" 0402 6870.21,670.83 r0 bottom value=0.1uF
C126 "GRM155R70J105MA12D" 0402 6755.41,788.94 r180 top value=1uF
C127 "GRM155R70J104KA01D" 0402 6870.21,788.94 r0 bottom value=0.1uF
C128 "GRM188Z71A106MA73D" 0603 6351.36,621.24 r180 bottom value=10uF
C129 "GRM155R70J103KA01D" 0402 6355.51,681.97 r180 bottom value=0.01uF
C130 "GRM155R70J105MA12D" 0402 6625,622.13 r90 top value=1uF
C131 "GRM155R70J104KA01D" 0402 6670,495 r270 bottom value=0.1uF
C132 "GRM155R70J105MA12D" 0402 6493.94,695.04 r0 top value=1uF
C133 "GRM155R70J104KA01D" 0402 6379.14,695.04 r180 top value=0.1uF
C134 "GRM155R71E104KE14D" 0402 1205.5,974.22 r180 bottom value=0.1uF
C135 "GRM155R71E103KA01D" 0402 325,1105.38 r270 bottom value=0.01uF
C136 "GRM155R71E104KE14D" 0402 1607.87,1117.23 r180 top value=0.1uF
C137 "GRM155R71E104KE14D" 0402 1607.87,1340 r180 top value=0.1uF
C138 "GRM155R71E104KE14D" 0402 1607.87,1723.86 r180 top value=0.1uF
C139 "GRM155R71E104KE14D" 0402 1199.79,1115.27 r0 top value=0.1uF
C140 "GRM155R71E104KE14D" 0402 1199.79,1340 r0 top value=0.1uF
C141 "GRM155R71E104KE14D" 0402 1186.93,1723.86 r0 top value=0.1uF
C142 "GRM155R71E104KE14D" 0402 1191.36,1554.93 r0 bottom value=0.1uF
C143 "GCM1555C1H8R0DA16D" 0402 1192.72,1141.33 r90 bottom
C144 "GCM1555C1H8R0DA16D" 0402 1192.72,1256.13 r270 bottom
C145 "GRM155R71E104KE14D" 0402 495.31,1188.47 r0 top value=0.1uF
C146 "GCM155C71A105KE38D" 0402_070 977.49,1025.32 r270 top value=1uF
C147 "GRM155R71E104KE14D" 0402 787.63,1021.22 r90 top value=0.1uF
C148 "GCM155C71A105KE38D" 0402_070 850.81,1627.63 r90 top value=1uF
C149 "GRM155R71E103KA01D" 0402 1190.5,1347.99 r0 bottom value=0.01uF
C150 "GRM155R71E104KE14D" 0402 480.5,1505.66 r0 top value=0.1uF
C151 "GRM155R71E104KE14D" 0402 360.82,1225.67 r270 bottom value=0.1uF
C152 "GRM155R71E103KA01D" 0402 415.82,1225.67 r270 bottom value=0.01uF
C153 "GRM155C81C225KE11D" 0402 1105,1221.57 r180 top value=2.2uF
C154 "GRM155R71E104KE14D" 0402 774.98,941.85 r180 bottom value=0.1uF
C155 "GRM155R71E104KE14D" 0402 774.98,941.85 r180 top value=0.1uF
C156 "GCM155C71A105KE38D" 0402_070 1105,1270 r0 top value=1uF
C157 "GRM21BZ71A226ME15L" 0805_HV 2477.33,1061.68 r180 top value=22uF
C158 "GRM21BZ71A226ME15L" 0805_HV 2477.33,1151.68 r180 top value=22uF
C159 "GRM32ER71A476ME15L" 1210_270 2460.42,1126.68 r180 bottom value=47uF
C160 "GRM188R71E474KA12D" 0603 2412.84,801.68 r270 top value=0.47uF
C161 "GRM188Z71C475KE21D" 0603 5664.06,1227.1 r90 bottom value=4.7uF
C162 "GCM155C71A105KE38D" 0402_070 5635.58,1227.04 r90 top value=1uF
C163 "GRM155R71E104KE14D" 0402 5695.21,1222.1 r90 top value=0.1uF
C164 "GRM32ER7YA106KA12K" 1210_270 6004.13,1223.43 r90 top value=10uF
C165 "GRM155R70J104KA01D" 0402 5909.13,1222.1 r90 top value=0.1uF
C166 "GRM155R72A272KA01D" 0402 5854.25,1128.43 r90 bottom value=2700pF
C167 "GRM32ER7YA106KA12K" 1210_270 2332.33,966.68 r90 top value=10uF
C168 "GRM32ER7YA106KA12K" 1210_270 2332.33,966.68 r90 bottom value=10uF
C169 "GRM21BZ71A226ME15L" 0805_HV 2839,1694.3 r180 top value=22uF
C170 "GRM21BZ71A226ME15L" 0805_HV 2839,1784.3 r180 top value=22uF
C171 "GRM32ER71A476ME15L" 1210_270 2822.09,1759.3 r180 bottom value=47uF
C172 "GRM188Z71C475KE21D" 0603 5664.13,1646.29 r90 bottom value=4.7uF
C173 "GCM155C71A105KE38D" 0402_070 5635.58,1643.07 r90 top value=1uF
C174 "GRM155R71E104KE14D" 0402 5695.21,1643.29 r90 top value=0.1uF
C175 "GRM32ER7YA106KA12K" 1210_270 6004.13,1642.62 r90 top value=10uF
C176 "GRM155R70J104KA01D" 0402 5909.13,1641.29 r90 top value=0.1uF
C177 "GRM188R71E474KA12D" 0603 2774.51,1434.3 r270 top value=0.47uF
C178 "GRM155R72A272KA01D" 0402 5854.25,1547.62 r90 bottom value=2700pF
C179 "GRM32ER7YA106KA12K" 1210_270 2694,1599.3 r90 bottom value=10uF
C180 "GRM32ER7YA106KA12K" 1210_270 2694,1599.3 r90 top value=10uF
C181 "GRM155R71E104KE14D" 0402 680.93,2065 r180 top value=0.1uF
C182 "GRM155R71E104KE14D" 0402 769.3,1977.87 r90 top value=0.1uF
C183 "GRM155R71E104KE14D" 0402 495.31,1965 r0 top value=0.1uF
C184 "GRM155R71E104KE14D" 0402 494.74,2015 r0 top value=0.1uF
C185 "GRM21BZ71A226ME15L" 0805_HV 2835,458.99 r180 top value=22uF
C186 "GRM155R71E104KE14D" 0402 2835,385.96 r180 top value=0.1uF
C187 "GCM155C71A105KE38D" 0402_070 2666.85,340.12 r90 top value=1uF
C188 "GRM155R71E104KE14D" 0402 2726.93,337.66 r90 top value=0.1uF
C189 "GRM1555C1E120JA01D" 0402 6541.38,1370 r180 bottom value=12pF
C190 "GRM1555C1E120JA01D" 0402 6648.62,1370 r0 bottom value=12pF
C191 "GRM188Z71A106MA73D" 0603 6279,1485.21 r90 top value=10uF
C192 "GRM155R70J103KA01D" 0402 6344,1481.38 r90 top value=0.01uF
C193 "GRM155R70J105MA12D" 0402 6556.28,1891.71 r90 top value=1uF
C194 "GRM155R70J104KA01D" 0402 6556.28,1895.08 r90 bottom value=0.1uF
C195 "GRM155R70J105MA12D" 0402 6498.94,1695.04 r0 top value=1uF
C196 "GRM155R70J104KA01D" 0402 6379.14,1695.04 r180 top value=0.1uF
C197 "GRM155R70J105MA12D" 0402 6751.41,1679.88 r180 top value=1uF
C198 "GRM155R70J104KA01D" 0402 6870.21,1679.88 r0 bottom value=0.1uF
C199 "GRM188Z71A106MA73D" 0603 6278.93,1156.97 r270 top value=10uF
C200 "GRM155R70J103KA01D" 0402 6334,1154.99 r270 top value=0.01uF
C201 "GRM155R70J105MA12D" 0402 6755.41,1620.83 r180 top value=1uF
C202 "GRM155R70J104KA01D" 0402 6870.21,1620.83 r0 bottom value=0.1uF
C203 "GRM155R70J105MA12D" 0402 6751.41,1738.94 r180 top value=1uF
C204 "GRM155R70J104KA01D" 0402 6870.21,1738.94 r0 bottom value=0.1uF
C205 "GRM188Z71A106MA73D" 0603 6351.36,1571.24 r180 bottom value=10uF
C206 "GRM155R70J103KA01D" 0402 6355.51,1631.97 r180 bottom value=0.01uF
C207 "GRM155R70J105MA12D" 0402 6625,1570.47 r90 top value=1uF
C208 "GRM155R70J104KA01D" 0402 6670,1445 r270 bottom value=0.1uF
C209 "GRM155R70J105MA12D" 0402 6498.94,1645.04 r0 top value=1uF
C210 "GRM155R70J104KA01D" 0402 6379.14,1645.04 r180 top value=0.1uF
C211 "GCM188R71H104KA57D" 0603 5880,230 r90 bottom value=0.1uF
C212 "GCM188R71H104KA57D" 0603 5880,480 r90 bottom value=0.1uF
C213 "GCM188R71H104KA57D" 0603 3890,2005 r270 bottom value=0.1uF
C214 "GCM1885C1H102JA16D" 0603 6199.18,230 r90 bottom value=1000pF
C215 "GRM1885C1H101JA01D" 0603 6124.18,230 r90 bottom value=100pF
C216 "GCM1885C1H102JA16D" 0603 6000,230 r90 bottom value=1000pF
C217 "GCM1885C1H102JA16D" 0603 6199.18,480 r90 bottom value=1000pF
C218 "GRM1885C1H101JA01D" 0603 6124.18,480 r90 bottom value=100pF
C219 "GCM1885C1H102JA16D" 0603 6000,480 r90 bottom value=1000pF
C220 "GCM1885C1H102JA16D" 0603 6492.17,290.82 r0 bottom value=1000pF
C221 "GCM1885C1H102JA16D" 0603 6197.13,494.67 r180 top value=1000pF
C222 "GCM155R71H472KA37D" 0402 6940,265 r90 top value=4700pF
C223 "GRM155R71E104KE14D" 0402 5483.66,140.04 r90 bottom value=0.1uF
C224 "GCM188R71H104KA57D" 0603 5642.05,93.47 r180 bottom value=0.1uF
C225 "GRM155R71E104KE14D" 0402 7182.8,136.46 r270 bottom value=0.1uF
C226 "GRM155R71E104KE14D" 0402 7010,60.4 r180 top value=0.1uF
C227 "GRM21BZ71E106KE15L" 0805_HV 285,906.68 r0 bottom value=10uF
C228 "GRM1555C1H150JA01D" 0402 658.65,1124.76 r180 top value=15pF
C229 "GR442QR73D102KW01L" 1808 731.46,180.12 r0 top value=1000pF
C230 "GR442QR73D102KW01L" 1808 227.89,1373.06 r270 bottom value=1000pF
C231 "GRM155C81C225KE11D" 0402 352.83,962.27 r90 top value=2.2uF
C232 "GCM155C71A105KE38D" 0402_070 660,1040.15 r90 top value=1uF
C233 "GRM155R71E104KE14D" 0402 577.56,962.27 r270 top value=0.1uF
C234 "GR442QR73D102KW01L" 1808 1398.86,1025 r0 bottom value=1000pF
C235 "GR442QR73D102KW01L" 1808 7235,1115 r0 top value=1000pF
C236 "C1608X7S1A335K080AC" 0603 2405.95,1413.5 r270 top value=3.3uF
C237 "GRM155R70J104KA01D" 0402 2345.94,1421.38 r270 top value=0.1uF
C238 "GRM155R71E104KE14D" 0402 5425,1178.69 r180 top value=0.1uF
C239 "GRM155R71E104KE14D" 0402 5339.88,764.77 r90 top value=0.1uF
C240 "GRM155R71E104KE14D" 0402 4670.38,1236.85 r90 top value=0.1uF
C241 "GRM155R71E104KE14D" 0402 4636.65,1588.39 r90 top value=0.1uF
C242 "GRM155R71E104KE14D" 0402 5036.38,1451.95 r180 top value=0.1uF
C243 "GRM155R71E104KE14D" 0402 4495.23,625.31 r90 bottom value=0.1uF
C244 "GRM155R71E104KE14D" 0402 4635,540.45 r270 bottom value=0.1uF
C245 "GRM155R71E104KE14D" 0402 4715,841.18 r270 top value=0.1uF
C246 "GRM155R71E104KE14D" 0402 4640,1712.48 r180 top value=0.1uF
C247 "GR442QR73D102KW01L" 1808 7185.15,2106.97 r0 top value=1000pF
C248 "GCM188R71C104KA37J" 0603 6064.09,698.38 r180 top value=0.1uF
C249 "GCM188R71C104KA37J" 0603 856.86,425.41 r0 top value=0.1uF
D1 "SMBJ6.5CA" SMB-Bi 1147.56,678.07 r270 bottom value=6.5V
D2 "150060VS75000" WL-SMCW_GREEN 1898.27,1001.7 r270 top value=Green
D3 "150060VS75000" WL-SMCW_GREEN 165,1531.39 r0 top value=Green
D4 "150060VS75000" WL-SMCW_GREEN 2812.72,2212.24 r90 top value=Green
D5 "150060VS75000" WL-SMCW_GREEN 2036.27,91.9 r270 top value=Green
D6 "150060VS75000" WL-SMCW_GREEN 2835,119.75 r0 top value=Green
D7 "150060VS75000" WL-SMCW_GREEN 2669.29,2208.31 r90 top value=Green
D8 "150060VS75000" WL-SMCW_GREEN 2529.29,2208.31 r90 top value=Green
D9 "150060VS75000" WL-SMCW_GREEN 2389.29,2208.31 r90 top value=Green
D10 "150060VS75000" WL-SMCW_GREEN 2249.29,2208.31 r90 top value=Green
D11 "150060VS75000" WL-SMCW_GREEN 2077.87,2208.31 r90 top value=Green
D12 "150060VS75000" WL-SMCW_GREEN 1937.87,2208.31 r90 top value=Green
D13 "150060VS75000" WL-SMCW_GREEN 1797.87,2208.31 r90 top value=Green
D14 "150060VS75000" WL-SMCW_GREEN 1677.87,2208.31 r90 top value=Green
D15 "TPD1E01B04DPYR" DPY0002A 4351.58,466.66 r180 top
D16 "TPD1E01B04DPYR" DPY0002A 1997.72,485.1 r180 top
DS1 "150060RS75000" WL-SMCW_RED 2703,1992.4 r180 top value=Red
DS2 "150060RS75000" WL-SMCW_RED 5930.69,2090.86 r90 top value=Red
DS3 "150060RS75000" WL-SMCW_RED 165,1614.41 r0 top value=Red
FB1 "BLM18EG121SN1D" FP-BLM18EG121SN1D_0603-MFG 4000.08,564.71 r180 bottom
FB2 "BLM18EG121SN1D" FP-BLM18EG121SN1D_0603-MFG 3621.02,485 r180 bottom
FB3 "BLM18EG121SN1D" FP-BLM18EG121SN1D_0603-MFG 6188.68,1310.55 r0 top
FB4 "BLM18EG121SN1D" FP-BLM18EG121SN1D_0603-MFG 6115.92,970.9 r0 top
FB5 "BLM18EG121SN1D" FP-BLM18EG121SN1D_0603-MFG 6188.68,1449.44 r0 top
FB6 "BLM18EG121SN1D" FP-BLM18EG121SN1D_0603-MFG 6188.68,1188.64 r0 top
FID1 "Fiducial" Fiducial10-20 6995.38,2165 r90 top
FID2 "Fiducial" Fiducial10-20 113.79,392.07 r90 top
FID3 "Fiducial" Fiducial10-20 113.79,1771.83 r90 top
J1 "PBC02SAAN" Sullins_PBC02SAAN 1395.54,1975 r180 top locked
J1/J3 "SSQ-110-03-T-D" BoosterPack_40pin_J1J3 2054.17,300 r270 bottom locked
J2 "DM3BT-DSF-PEJS" Hirose_DM3BT-DSF-PEJS 570,362.52 r180 bottom locked
J2/J4 "SSQ-110-03-T-D" BoosterPack_40pin_J2J4 2054.17,2000 r270 bottom locked
J5 "2012670005" FP-2012670005_CONN_USB_9MM39_8MM21-MFG 1118.35,154.53 r0 top locked
J5/J7 "SSQ-110-03-T-D" BoosterPack_40pin_J5J7 4554.17,300 r270 bottom locked
J6 "FH12A-40S-0.5SH(55)" FP-FH12A-40S-0.5SH(55)_FFC40-MFG 945.63,2200 r180 bottom locked
J6/J8 "SSQ-110-03-T-D" BoosterPack_40pin_J6J8 4554.17,2000 r270 bottom locked
J7 "LPJG16314A4NL" FP-LPJG16314A4NL_CONN_RJ45-MFG 7444,655 r90 top locked
J8 "LPJG16314A4NL" FP-LPJG16314A4NL_CONN_RJ45-MFG 7444,1645 r90 top locked
J9 "PBC02SAAN" Sullins_PBC02SAAN 1445,136.05 r180 top
J10 "PBC02SAAN" Sullins_PBC02SAAN 1445,360 r0 top
J11 "PBC03SAAN" PBC03SAAN 5304.17,250 r180 top locked
J12 "PBC03SAAN" PBC03SAAN 5304.17,2050 r180 top locked
J13 "PBC02SAAN" Sullins_PBC02SAAN 5235.83,543.25 r0 top
J14 "PBC02SAAN" Sullins_PBC02SAAN 5367.11,543.25 r0 top
J15 "PBC02SAAN" Sullins_PBC02SAAN 6327.06,165 r180 top
J16 "PBC02SAAN" Sullins_PBC02SAAN 6327.06,415 r180 top
J17 "PBC02SAAN" Sullins_PBC02SAAN 1668.62,1023.77 r90 top
J18 "PBC02SAAN" Sullins_PBC02SAAN 2695,634.47 r0 top
J23 "PRPC005DAAN-RC" Sullins_xxPC005DAAN-RC 3604.17,2000 r90 top locked
J24 "PEC05SAAN" Sullins_PxC05SAAN 5999.18,115 r180 top locked
J25 "PEC05SAAN" Sullins_PxC05SAAN 5999.18,365 r180 top locked
J33 "OSTTE030161" On-Shore_OSTTE030161 6654.17,183.86 r0 top locked
J34 "1051640001" Molex_1051640001 0,1044.08 r270 top
L1 "BLM21PG300SH1D" 0805_HV 1322.44,547.65 r0 top value="30 ohm"
L2 "74438356022" WE-MAPI_4020 2645.75,1000.74 r90 top value=2.2uH
L3 "74438356022" WE-MAPI_4020 3007.43,1633.36 r90 top value=2.2uH
L4 "74405020100" FP-74405020100_SMT_IND_2MM0_1MM6-MFG 2935,338.84 r90 top
LBL1 "THT-14-423-10" Label_650x200 6610,2187.06 r0 top
Logo1 "CE Mark" CE_Mark_5mm 735,1417.13 r0 top
Logo2 "Texas Instruments" TI_Stacked_Overlay_Small 5135,1778.31 r0 top locked
Logo3 "FCC disclaimer" FCC_disclaimer 9836.36,4289 r270 bottom
Logo4 "WEEE logo" WEEE_Minimum 6005,838.02 r180 bottom
Q1 "IRLML6401TRPBF" SOT-23 852.98,1907.76 r270 bottom value=-12V
Q2 "IRLML6401TRPBF" SOT-23 1062.25,2017.02 r270 top value=-12V
Q3 "IRLML6401TRPBF" SOT-23 1201.12,2017.02 r270 top value=-12V
Q4 "BSS123" SOT-23 7274.1,1140 r270 bottom value=100V
Q5 "BSS123" SOT-23 7324,113.66 r90 top value=100V
Q6 "BSS123" SOT-23 7324,113.66 r90 bottom value=100V
Q7 "BSS123" SOT-23 7340,2165 r270 bottom value=100V
Q8 "BSS123" SOT-23 7433.87,1140.67 r90 bottom value=100V
Q9 "BSS123" SOT-23 7580.33,1139.39 r90 bottom value=100V
Q10 "BSS223PWH6327" SOT-323 2848,1981 r270 top value=-20V
Q11 "BSS123W-7-F" SOT-323 5828,2065.27 r0 top value=100V
Q13 "BSS123W-7-F" SOT-323 1930,123.39 r0 top value=100V
R1 "ERJ-2RKF1002X" 0402 3237.47,633.24 r270 top value=10.0k
R2 "CRCW04022K67FKED" 0402 3337.66,633.24 r90 top value=2.67k
R3 "ERJ-2GE0R00X" 0402L 3575.19,468.53 r90 top value=0
R4 "ERJ-2GE0R00X" 0402L 3240.9,969.06 r180 top value=0
R5 "ERJ-2GE0R00X" 0402 2048.11,1654.66 r270 bottom value=0
R6 "ERJ-2RKF1002X" 0402 2162.72,1229.13 r180 top value=10.0k
R7 "ERJ-2GE0R00X" 0402L 3410,1612.48 r90 top value=0
R8 "ERJ-2RKF1002X" 0402 3563.14,109.77 r0 bottom value=10.0k
R9 "ERJ-2GE0R00X" 0402L 3074.77,1238.11 r0 top value=0
R10 "ERJ-2RKF1002X" 0402 3215,358.58 r0 top value=10.0k
R11 "ERJ-2RKF1002X" 0402 3270,530.76 r0 top value=10.0k
R12 "ERJ-2GE0R00X" 0402L 3074.77,1135.05 r0 top value=0
R13 "ERJ-2GE0R00X" 0402L 3074.77,1181.64 r0 top value=0
R14 "ERJ-2RKF1002X" 0402 3411.93,119.51 r0 top value=10.0k
R15 "ERJ-2RKF1002X" 0402 3411.93,169.51 r0 top value=10.0k
R16 "ERJ-2RKF1002X" 0402 3411.93,219.51 r0 top value=10.0k
R17 "ERJ-2RKF1002X" 0402 3411.93,269.51 r0 top value=10.0k
R18 "ERJ-2GE0R00X" 0402 2140.8,1039.07 r0 top value=0
R19 "ERJ-2RKF49R9X" 0402 2262.84,767.39 r270 top value=49.9
R20 "ERJ-2RKF1002X" 0402 2140.8,1094.07 r180 top value=10.0k
R21 "ERJ-2GEJ102X" 0402 1545,1829.63 r90 top value=1.0k
R22 "ERJ-2GEJ102X" 0402 3920,119.51 r180 top value=1.0k
R23 "ERJ-2GEJ102X" 0402 3920,169.51 r180 top value=1.0k
R24 "ERJ-2GEJ102X" 0402 3920,219.51 r180 top value=1.0k
R25 "ERJ-2GEJ102X" 0402 3920,269.51 r180 top value=1.0k
R26 "ERJ-2GE0R00X" 0402L 2810,828.96 r270 top value=0
R27 "ERJ-2GE0R00X" 0402L 2760,828.96 r270 top value=0
R28 "ERJ-2GE0R00X" 0402L 2830,1339.27 r180 top value=0
R29 "ERJ-2GE0R00X" 0402L 2830,1293.54 r180 top value=0
R30 "ERJ-2GE0R00X" 0402L 2860,828.96 r270 top value=0
R31 "CRCW040247K5FKED" 0402 3255,893.53 r180 top value=47.5k
R32 "ERJ-6ENF1004V" 0805_HV 749.55,73.93 r180 top value=1.00Meg
R33 "ERJ-2GE0R00X" 0402L 3669,1612.48 r90 top value=0
R34 "ERJ-2GE0R00X" 0402L 3573,1612.48 r90 top value=0
R35 "ERJ-2GE0R00X" 0402L 3611,1612.48 r90 top value=0
R36 "ERJ-2GE0R00X" 0402L 3535,1612.48 r90 top value=0
R37 "ERJ-2GE0R00X" 0402L 3497,1612.48 r90 top value=0
R38 "ERJ-2GE0R00X" 0402L 3449,1612.48 r90 top value=0
R39 "CRCW040210K0FKED" 0402L 867.24,754.8 r180 top value=10.0k
R40 "CRCW040210K0FKED" 0402L 185,594.53 r180 top value=10.0k
R41 "CRCW040210K0FKED" 0402L 3678.01,1730 r90 bottom value=10.0k
R42 "ERJ-2RKF1002X" 0402 3164.53,914.8 r270 top value=10.0k
R43 "ERJ-2RKF1002X" 0402 2776.98,1285 r0 bottom value=10.0k
R44 "ERJ-2GE0R00X" 0402L 3872.63,611.52 r90 top value=0
R45 "ERJ-2GE0R00X" 0402L 3528.72,469.92 r90 top value=0
R46 "ERJ-2GE0R00X" 0402L 3344.16,1600.48 r270 top value=0
R47 "ERJ-2GE0R00X" 0402L 3355,1534 r0 top value=0
R48 "ERJ-2GE0R00X" 0402L 3234.69,1495 r0 bottom value=0
R49 "ERJ-2GE0R00X" 0402L 3297.5,1415.5 r0 top value=0
R50 "ERJ-2GE0R00X" 0402L 3355,1493.5 r0 top value=0
R51 "ERJ-2GE0R00X" 0402L 3355,1453.5 r0 top value=0
R52 "ERJ-2GE0R00X" 0402L 3210.5,1391.92 r270 top value=0
R53 "ERJ-2GE0R00X" 0402L 3075,1336.34 r0 bottom value=0
R54 "ERJ-2GE0R00X" 0402L 3209.68,1317.26 r0 top value=0
R55 "CRCW04024K70JNED" 0402 2404.17,146.38 r270 top value=4.7k
R56 "CRCW04024K70JNED" 0402 2504.17,146.38 r270 top value=4.7k
R57 "ERJ-2GE0R00X" 0402L 3209.68,1274.26 r0 top value=0
R58 "ERJ-2GE0R00X" 0402L 3209.68,1231.26 r0 top value=0
R59 "ERJ-2GE0R00X" 0402L 3075,1181.51 r0 bottom value=0
R60 "ERJ-2GE0R00X" 0402L 3077.77,1135.05 r0 bottom value=0
R61 "ERJ-2GE0R00X" 0402L 4955.28,975.79 r0 bottom value=0
R62 "ERJ-2GE0R00X" 0402L 4955.28,1111.7 r0 bottom value=0
R63 "CRCW04024K70JNED" 0402 4959.21,1019.06 r0 bottom value=4.7k
R64 "CRCW04024K70JNED" 0402 4959.21,1068.43 r0 bottom value=4.7k
R65 "ERJ-2GE0R00X" 0402L 4312.25,840.82 r180 top value=0
R66 "ERJ-2GE0R00X" 0402L 4312.25,878.82 r180 top value=0
R67 "ERJ-2GE0R00X" 0402L 4312.25,916.82 r180 top value=0
R68 "ERJ-2GE0R00X" 0402L 4312.25,952.82 r180 top value=0
R69 "ERJ-2GE0R00X" 0402L 4312.25,1030.82 r180 top value=0
R70 "ERJ-2GE0R00X" 0402L 4312.25,989.82 r180 top value=0
R71 "ERJ-2GE0R00X" 0402L 4312.25,1071.65 r180 top value=0
R72 "ERJ-2GE0R00X" 0402L 4451.61,1086.73 r180 top value=0
R73 "CRCW04024K70JNED" 0402 4564.79,1010.55 r180 bottom value=4.7k
R74 "CRCW04024K70JNED" 0402 4564.79,1074.9 r180 bottom value=4.7k
R75 "ERJ-2GE0R00X" 0402L 4451.61,1029.87 r180 bottom value=0
R76 "ERJ-2GE0R00X" 0402L 4452.24,1029.87 r180 top value=0
R77 "ERJ-2GE0R00X" 0402L 4312.25,1191.33 r180 top value=0
R78 "ERJ-2GE0R00X" 0402L 4557.16,1313.21 r180 top value=0
R79 "ERJ-2GE0R00X" 0402L 4449.67,1086.88 r180 bottom value=0
R80 "ERJ-2GE0R00X" 0402L 4312.25,1151.33 r180 top value=0
R81 "ERJ-2GE0R00X" 0402L 4312.25,1450.76 r180 top value=0
R82 "ERJ-2GE0R00X" 0402L 4187,1612.48 r270 top value=0
R83 "ERJ-2GE0R00X" 0402L 4320,1333.3 r180 top value=0
R84 "ERJ-2GE0R00X" 0402L 4312.25,1410.76 r180 top value=0
R85 "ERJ-2GE0R00X" 0402L 4149,1612.48 r270 top value=0
R86 "ERJ-2GE0R00X" 0402L 4111,1612.48 r270 top value=0
R87 "ERJ-2GE0R00X" 0402L 4078.97,1769.24 r180 bottom value=0
R88 "ERJ-2GE0R00X" 0402L 4078.97,1812.24 r180 bottom value=0
R89 "ERJ-2GE0R00X" 0402L 592.82,324.31 r0 top value=0
R90 "ERJ-2GE0R00X" 0402L 592.82,364.41 r0 top value=0
R91 "CRCW0402200KJNED" 0402 587.51,263.69 r0 top value=200k
R92 "ERJ-2RKF1002X" 0402 669.95,404.69 r270 top value=10.0k
R93 "ERJ-2RKF1002X" 0402 669.95,294.31 r90 top value=10.0k
R94 "CRCW0402909KFKED" 0402 427.85,260.08 r180 top value=909k
R95 "CRCW04024K70JNED" 0402 396.4,312.6 r0 top value=4.7k
R96 "ERJ-2GEJ102X" 0402 5986.5,820 r270 top value=1.0k
R97 "ERJ-2GEJ102X" 0402 523.29,463.41 r270 top value=1.0k
R98 "ERJ-2RKF1002X" 0402 1645,663.27 r0 top value=10.0k
R99 "ERJ-2GE0R00X" 0402L 3074.77,1079.62 r0 top value=0
R100 "ERJ-2GE0R00X" 0402 6375.51,745.04 r0 bottom value=0
R101 "ERJ-2GE0R00X" 0402 6506.28,945 r270 bottom value=0
R102 "ERJ-2GE0R00X" 0402 6375.51,795.04 r0 bottom value=0
R103 "ERJ-2GE0R00X" 0402 6375.51,845.04 r0 bottom value=0
R104 "ERJ-2GE0R00X" 0402 6406.28,945 r270 bottom value=0
R105 "ERJ-2GE0R00X" 0402 6456.28,945 r270 bottom value=0
R106 "ERJ-2GE0R00X" 0402 6493.31,940.44 r90 top value=0
R107 "ERJ-2RKF1152X" 0402 6815,553.37 r90 bottom value=11.5k
R108 "CRCW04022K49FKED" 0402 6251.3,802.65 r180 top value=2.49k
R109 "CRCW04022K49FKED" 0402 6251.38,880.96 r180 top value=2.49k
R110 "CRCW04022K49FKED" 0402 6729.39,950.08 r90 top value=2.49k
R111 "CRCW04022K49FKED" 0402 6796.28,949.68 r90 top value=2.49k
R112 "CRCW04022K49FKED" 0402 6674.39,950.08 r90 top value=2.49k
R113 "CRCW04022K49FKED" 0402 6506.28,1059.68 r90 top value=2.49k
R114 "CRCW04022K49FKED" 0402 6520,495 r270 top value=2.49k
R115 "CRCW04022K49FKED" 0402 6383.01,1062.96 r90 top value=2.49k
R116 "CRCW04022K49FKED" 0402 6443.01,1062.97 r90 top value=2.49k
R117 "ERJ-2GE0R00X" 0402 6570,495 r90 bottom value=0
R118 "ERJ-2GE0R00X" 0402 6520,495 r90 bottom value=0
R119 "ERJ-2GE0R00X" 0402 6620,495 r90 bottom value=0
R120 "CRCW04022K49FKED" 0402 6251.3,802.65 r0 bottom value=2.49k
R121 "CRCW04022K49FKED" 0402 6251.49,880.85 r0 bottom value=2.49k
R122 "CRCW04022K49FKED" 0402 6729.39,950.08 r270 bottom value=2.49k
R123 "CRCW04022K49FKED" 0402 6848,949.68 r270 top value=2.49k
R124 "CRCW04022K49FKED" 0402 6674.39,950.08 r270 bottom value=2.49k
R125 "CRCW04022K49FKED" 0402 6506.28,1059.68 r270 bottom value=2.49k
R126 "CRCW04022K49FKED" 0402 6570.85,495 r90 top value=2.49k
R127 "CRCW04022K49FKED" 0402 6379.14,1062.97 r270 bottom value=2.49k
R128 "CRCW04022K49FKED" 0402 6443.01,1062.97 r270 bottom value=2.49k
